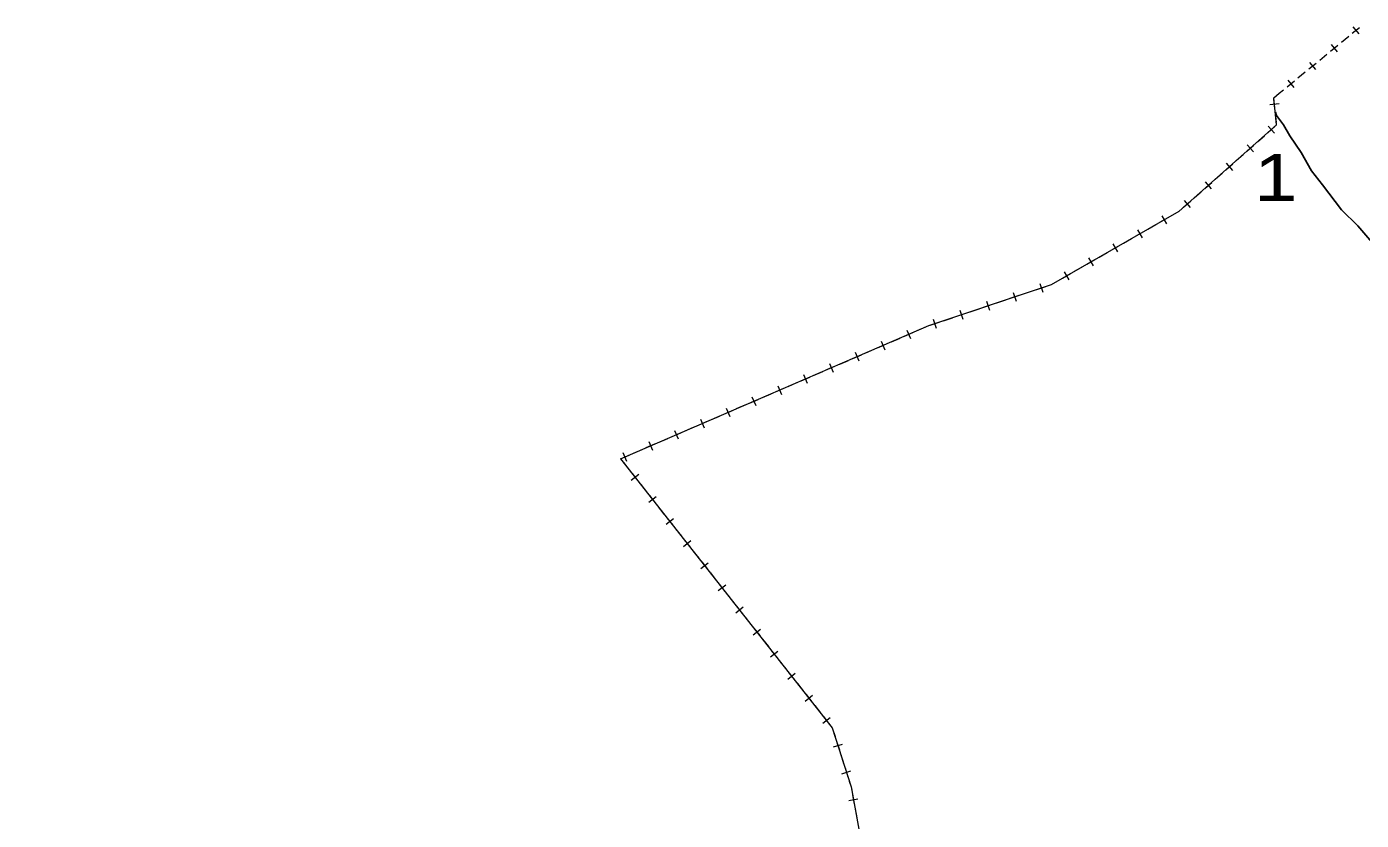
# Model space of a CAD drawing. Extents: x 476989 to 498418, y 4381813 to 4416555.
# Drawn here: x 484108 to 485532, y 4387982 to 4388829 of the extents above; entities that cross this region are included whole.
import ezdxf
from ezdxf.enums import TextEntityAlignment as Align

# ---------------------------------------------------------------- set-up
doc = ezdxf.new("R2010")
doc.units = 0
doc.header["$LTSCALE"] = 20
doc.layers.add('34', color=7, linetype='Continuous', lineweight=13)
doc.layers.add('6', color=7, linetype='Continuous', lineweight=25)

msp = doc.modelspace()

# ---------------------------------------------------------------- linework, layer by layer
at = {"layer": '34'}
for p, q in [((485511.18, 4388812.24), (485518.91, 4388818.58)), ((485522.77, 4388821.75), (485530.5, 4388828.09)), ((485523.46, 4388828.78), (485529.8, 4388821.05)), ((485499.58, 4388802.72), (485507.31, 4388809.06)), ((485500.28, 4388809.76), (485506.62, 4388802.03)), ((485476.4, 4388783.69), (485484.13, 4388790.04)), ((485477.09, 4388790.73), (485483.44, 4388783)), ((485488, 4388793.21), (485495.73, 4388799.55)), ((485464.81, 4388774.19), (485472.54, 4388780.53)), ((485444.8, 4388757.76), (485449.36, 4388761.5)), ((485453.22, 4388764.67), (485460.95, 4388771.01)), ((485453.91, 4388771.71), (485460.26, 4388763.98)), ((485434.71, 4388745.92), (485444.65, 4388746.95)), ((485440.19, 4388741.47), (485439.16, 4388751.41)), ((485441.63, 4388755.16), (485444.8, 4388757.76)), ((485441.74, 4388726.56), (485440.71, 4388736.5)), ((485432.69, 4388715.76), (485440.18, 4388722.39)), ((485433.12, 4388722.82), (485439.75, 4388715.33)), ((485421.46, 4388705.83), (485428.95, 4388712.46)), ((485399, 4388685.96), (485406.49, 4388692.59)), ((485410.23, 4388695.89), (485417.72, 4388702.52)), ((485410.66, 4388702.95), (485417.28, 4388695.46)), ((485387.76, 4388676.02), (485395.25, 4388682.65)), ((485388.2, 4388683.08), (485394.82, 4388675.59)), ((485365.3, 4388656.15), (485372.79, 4388662.78)), ((485365.73, 4388663.21), (485372.36, 4388655.72)), ((485376.54, 4388666.09), (485384.03, 4388672.72)), ((485354.07, 4388646.22), (485361.56, 4388652.85)), ((485342.84, 4388636.28), (485350.33, 4388642.91)), ((485343.27, 4388643.34), (485349.9, 4388635.85)), ((485304.59, 4388612.84), (485313.26, 4388617.81)), ((485317.59, 4388620.29), (485326.26, 4388625.27)), ((485319.44, 4388627.12), (485324.41, 4388618.44)), ((485291.58, 4388605.37), (485300.25, 4388610.35)), ((485293.42, 4388612.2), (485298.4, 4388603.52)), ((485265.56, 4388590.45), (485274.23, 4388595.43)), ((485267.41, 4388597.28), (485272.38, 4388588.6)), ((485278.57, 4388597.92), (485287.25, 4388602.89)), ((485239.54, 4388575.53), (485248.22, 4388580.51)), ((485241.39, 4388582.36), (485246.37, 4388573.68)), ((485252.56, 4388583), (485261.23, 4388587.97)), ((485213.53, 4388560.61), (485222.2, 4388565.59)), ((485215.38, 4388567.44), (485220.35, 4388558.76)), ((485226.54, 4388568.08), (485235.22, 4388573.05)), ((485171.96, 4388543.91), (485181.44, 4388547.09)), ((485186.17, 4388548.68), (485195.65, 4388551.87)), ((485189.32, 4388555.02), (485192.5, 4388545.54)), ((485129.31, 4388529.59), (485138.79, 4388532.77)), ((485132.46, 4388535.92), (485135.64, 4388526.44)), ((485143.53, 4388534.36), (485153.01, 4388537.55)), ((485157.74, 4388539.13), (485167.22, 4388542.32)), ((485160.89, 4388545.47), (485164.07, 4388535.99)), ((485086.67, 4388515.26), (485096.15, 4388518.45)), ((485100.88, 4388520.04), (485110.36, 4388523.22)), ((485104.03, 4388526.37), (485107.21, 4388516.89)), ((485115.1, 4388524.81), (485124.58, 4388528)), ((485047.48, 4388505.3), (485051.45, 4388496.11)), ((485058.65, 4388504.67), (485067.83, 4388508.63)), ((485072.45, 4388510.49), (485081.93, 4388513.67)), ((485075.6, 4388516.82), (485078.79, 4388507.34)), ((485017.34, 4388486.84), (485026.52, 4388490.8)), ((485019.95, 4388493.41), (485023.91, 4388484.23)), ((485031.11, 4388492.78), (485040.29, 4388496.75)), ((485044.87, 4388498.72), (485054.05, 4388502.69)), ((484989.8, 4388474.95), (484998.99, 4388478.92)), ((484992.41, 4388481.53), (484996.38, 4388472.35)), ((485003.58, 4388480.9), (485012.76, 4388484.86)), ((484962.27, 4388463.07), (484971.45, 4388467.03)), ((484964.88, 4388469.64), (484968.84, 4388460.46)), ((484976.04, 4388469.01), (484985.22, 4388472.98)), ((484920.97, 4388445.25), (484930.15, 4388449.21)), ((484934.73, 4388451.19), (484943.92, 4388455.15)), ((484937.34, 4388457.76), (484941.31, 4388448.58)), ((484948.51, 4388457.13), (484957.69, 4388461.09)), ((484882.27, 4388433.99), (484886.24, 4388424.81)), ((484893.44, 4388433.36), (484902.62, 4388437.32)), ((484907.2, 4388439.3), (484916.38, 4388443.26)), ((484909.81, 4388445.87), (484913.77, 4388436.69)), ((484852.13, 4388415.53), (484861.31, 4388419.5)), ((484854.74, 4388422.11), (484858.7, 4388412.92)), ((484865.9, 4388421.48), (484875.08, 4388425.44)), ((484879.66, 4388427.42), (484888.85, 4388431.38)), ((484824.6, 4388403.65), (484833.78, 4388407.61)), ((484827.2, 4388410.22), (484831.17, 4388401.04)), ((484838.37, 4388409.59), (484847.55, 4388413.56)), ((484797.06, 4388391.76), (484806.24, 4388395.73)), ((484799.67, 4388398.34), (484803.63, 4388389.16)), ((484810.83, 4388397.71), (484820.01, 4388401.67)), ((484755.76, 4388373.94), (484764.94, 4388377.9)), ((484769.53, 4388379.88), (484778.71, 4388383.84)), ((484772.13, 4388386.45), (484776.1, 4388377.27)), ((484783.3, 4388385.82), (484792.48, 4388389.79)), ((484742, 4388368), (484751.17, 4388371.96)), ((484744.6, 4388374.57), (484748.56, 4388365.39)), ((484745.09, 4388364.07), (484751.28, 4388356.22)), ((484753.54, 4388345.27), (484761.39, 4388351.45)), ((484754.37, 4388352.29), (484760.56, 4388344.43)), ((484763.65, 4388340.5), (484769.84, 4388332.65)), ((484772.1, 4388321.7), (484779.95, 4388327.88)), ((484772.93, 4388328.72), (484779.12, 4388320.86)), ((484782.21, 4388316.93), (484788.4, 4388309.08)), ((484791.49, 4388305.15), (484797.68, 4388297.29)), ((484790.66, 4388298.13), (484798.52, 4388304.31)), ((484800.77, 4388293.36), (484806.96, 4388285.51)), ((484809.22, 4388274.56), (484817.08, 4388280.74)), ((484810.05, 4388281.58), (484816.24, 4388273.72)), ((484819.33, 4388269.79), (484825.52, 4388261.94)), ((484827.78, 4388250.99), (484835.64, 4388257.17)), ((484828.61, 4388258.01), (484834.8, 4388250.15)), ((484837.89, 4388246.22), (484844.08, 4388238.37)), ((484846.34, 4388227.42), (484854.2, 4388233.6)), ((484847.17, 4388234.44), (484853.36, 4388226.58)), ((484856.45, 4388222.65), (484862.64, 4388214.8)), ((484864.9, 4388203.85), (484872.76, 4388210.03)), ((484865.73, 4388210.87), (484871.92, 4388203.01)), ((484875.01, 4388199.08), (484881.2, 4388191.23)), ((484883.46, 4388180.28), (484891.32, 4388186.46)), ((484884.29, 4388187.3), (484890.48, 4388179.44)), ((484893.57, 4388175.52), (484899.76, 4388167.66)), ((484902.02, 4388156.71), (484909.88, 4388162.9)), ((484902.85, 4388163.73), (484909.04, 4388155.87)), ((484912.13, 4388151.95), (484918.32, 4388144.09)), ((484920.58, 4388133.14), (484928.44, 4388139.33)), ((484921.41, 4388140.16), (484927.6, 4388132.3)), ((484930.69, 4388128.38), (484936.88, 4388120.52)), ((484939.14, 4388109.57), (484947, 4388115.76)), ((484939.97, 4388116.59), (484946.16, 4388108.73)), ((484949.25, 4388104.81), (484955.44, 4388096.95)), ((484957.7, 4388086), (484965.56, 4388092.19)), ((484958.53, 4388093.02), (484964.72, 4388085.16)), ((484969.19, 4388060.71), (484978.73, 4388063.74)), ((484972.45, 4388066.99), (484975.47, 4388057.46)), ((484976.99, 4388052.69), (484980.01, 4388043.16)), ((484978.27, 4388032.12), (484987.8, 4388035.14)), ((484981.52, 4388038.4), (484984.55, 4388028.87)), ((484985.5, 4388003.73), (484995.34, 4388005.51)), ((484989.53, 4388009.54), (484991.31, 4387999.7)), ((484992.2, 4387994.78), (484993.99, 4387984.94))]:
    msp.add_line(p, q, dxfattribs=at)
for points in [[(484742, 4388368), (485071, 4388510), (485202, 4388554), (485338, 4388632), (485442, 4388724), (485439, 4388753), (485444.8, 4388757.76)], [(485330.6, 4388627.76), (485338, 4388632), (485339.1, 4388632.98)], [(485200.39, 4388553.46), (485202, 4388554), (485209.2, 4388558.13)], [(484742, 4388368), (484968, 4388081), (484988, 4388018), (485030, 4387786), (485030, 4387747), (484843, 4387760), (484712, 4387762), (484623, 4387793), (484342, 4387807), (484273, 4387819), (484108.44, 4387807.03)], [(484967.81, 4388081.24), (484968, 4388081), (484970.93, 4388071.76)], [(484986.06, 4388024.1), (484988, 4388018), (484988.64, 4388014.46)]]:
    msp.add_lwpolyline(points, dxfattribs=at)
at = {"layer": '6'}
msp.add_lwpolyline([(485440.7, 4388737.5), (485441.99, 4388734.08), (485449.36, 4388724.07), (485456.08, 4388712.46), (485468.1, 4388694.6), (485479.36, 4388675.04), (485491.14, 4388660.05), (485511.34, 4388633.52), (485528.76, 4388616.39), (485543.57, 4388599.11)], dxfattribs=at)

# ---------------------------------------------------------------- texts
at = {"layer": '6', "width": 1.25}
msp.add_text('1', height=50, dxfattribs=at).set_placement((485441.14, 4388643), align=Align.CENTER)

doc.saveas('drawing.dxf')
